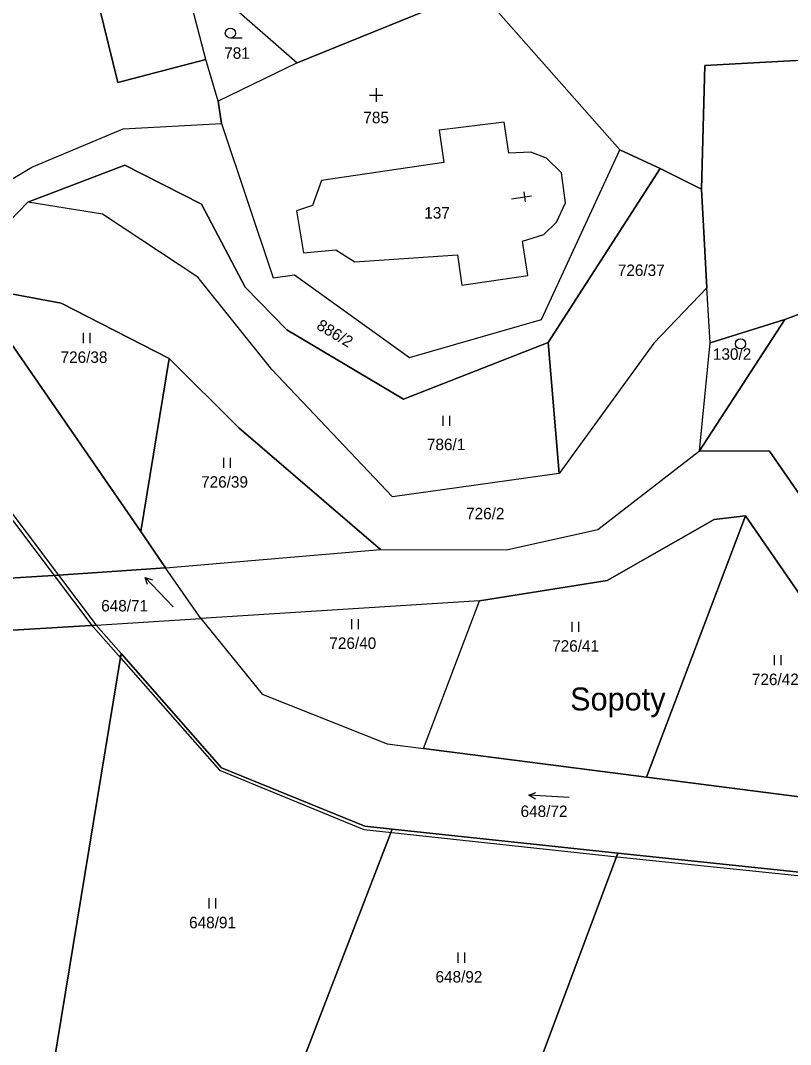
# Model space of a CAD drawing. Extents: x -654083 to -650132, y -1099819 to -1096699.
# Drawn here: x -653142.9 to -653028.7, y -1098349.3 to -1098197.5 of the extents above; entities that cross this region are included whole.
import ezdxf

# ---------------------------------------------------------------- set-up
doc = ezdxf.new("R2010")
doc.units = 0
for name, color, linetype in [('Obvody jako plochy', 7, 'Continuous'), ('Ostatní hranice', 7, 'Continuous'), ('Ostatní mapové značky 1', 7, 'Continuous'), ('Parcelní čísla', 7, 'Continuous'), ('Značky kultur', 7, 'Continuous')]:
    doc.layers.add(name, color=color, linetype=linetype)

msp = doc.modelspace()

# ---------------------------------------------------------------- linework, layer by layer
at = {"layer": 'Obvody jako plochy'}
for points in [[(-653140.06, -1098171.16), (-653142.69, -1098158.75), (-653160.81, -1098164.87), (-653165.45, -1098167.24), (-653166.29, -1098184.39), (-653163.28, -1098198.26), (-653156.38, -1098205.89), (-653150.52, -1098224.84), (-653141.18, -1098219.21), (-653127.65, -1098213.56), (-653113.09, -1098212.74), (-653113.57, -1098209.43), (-653115.41, -1098203.29), (-653128.45, -1098206.67), (-653133.29, -1098186.91), (-653120.36, -1098183.92), (-653123.61, -1098174.68), (-653124.29, -1098173.63), (-653125.55, -1098167.69), (-653129.48, -1098168.54)], [(-653079.59, -1098187.95), (-653094, -1098190.37), (-653107.31, -1098170.36), (-653104.62, -1098168.32), (-653108.47, -1098163.66), (-653111.39, -1098164.65), (-653125.55, -1098167.69), (-653124.29, -1098173.63), (-653123.61, -1098174.68), (-653115.58, -1098183.94), (-653113.62, -1098191.47), (-653118.1, -1098192.78), (-653120.36, -1098183.92), (-653133.29, -1098186.91), (-653128.45, -1098206.67), (-653115.41, -1098203.29), (-653117.7, -1098194.34), (-653112.47, -1098194.44), (-653101.85, -1098203.76), (-653075.01, -1098192.86)], [(-653128.45, -1098206.67), (-653115.41, -1098203.29), (-653117.7, -1098194.34), (-653118.1, -1098192.78), (-653120.36, -1098183.92), (-653133.29, -1098186.91)], [(-653054.02, -1098216.68), (-653075.01, -1098192.86), (-653101.85, -1098203.76), (-653113.57, -1098209.43), (-653113.09, -1098212.74), (-653105.4, -1098235.64), (-653102.24, -1098235.17), (-653085.2, -1098247.42), (-653065.64, -1098241.83)], [(-653101.85, -1098203.76), (-653113.57, -1098209.43), (-653115.41, -1098203.29), (-653117.7, -1098194.34), (-653112.47, -1098194.44)], [(-653009.72, -1098222.06), (-653004.59, -1098221.2), (-653000.75, -1098231.78), (-653018.05, -1098237.54), (-653029.55, -1098241.81), (-653040.62, -1098245.28), (-653041.08, -1098237.12), (-653041.91, -1098222.49), (-653041.39, -1098204.15), (-653027.83, -1098203.43), (-653014.45, -1098203.06), (-653011.55, -1098222.36)], [(-653127.42, -1098218.94), (-653141.81, -1098224.4), (-653151.72, -1098234.65), (-653155.1, -1098229.74), (-653150.52, -1098224.84), (-653141.18, -1098219.21), (-653127.65, -1098213.56), (-653113.09, -1098212.74), (-653105.4, -1098235.64), (-653102.24, -1098235.17), (-653085.2, -1098247.42), (-653065.64, -1098241.83), (-653054.02, -1098216.68), (-653048.02, -1098219.45), (-653064.64, -1098245.21), (-653086.06, -1098253.64), (-653103.37, -1098243.32), (-653109.58, -1098237.03), (-653116.05, -1098224.73)], [(-653063.4, -1098227.37), (-653062.04, -1098224.53), (-653062.64, -1098220.09), (-653064.88, -1098217.9), (-653067.21, -1098216.99), (-653070.45, -1098217.14), (-653071.17, -1098212.57), (-653080.78, -1098213.77), (-653080.08, -1098218.55), (-653098.25, -1098221.22), (-653099.57, -1098224.91), (-653101.96, -1098225.69), (-653100.91, -1098231.95), (-653096.13, -1098231.5), (-653093.28, -1098233.27), (-653078.09, -1098232.25), (-653077.44, -1098236.72), (-653067.67, -1098235.29), (-653068.42, -1098230.21), (-653065.25, -1098229.21)], [(-653078.09, -1098232.25), (-653077.44, -1098236.72), (-653067.67, -1098235.29), (-653068.42, -1098230.21), (-653065.25, -1098229.21), (-653063.4, -1098227.37), (-653062.04, -1098224.53), (-653062.64, -1098220.09), (-653064.88, -1098217.9), (-653067.21, -1098216.99), (-653070.45, -1098217.14), (-653071.17, -1098212.57), (-653080.78, -1098213.77), (-653080.08, -1098218.55), (-653098.25, -1098221.22), (-653099.57, -1098224.91), (-653101.96, -1098225.69), (-653100.91, -1098231.95), (-653096.13, -1098231.5), (-653093.28, -1098233.27)], [(-653068.42, -1098230.21), (-653065.25, -1098229.21), (-653063.4, -1098227.37), (-653062.04, -1098224.53), (-653062.64, -1098220.09), (-653064.88, -1098217.9), (-653067.21, -1098216.99), (-653070.45, -1098217.14), (-653071.17, -1098212.57), (-653080.78, -1098213.77), (-653080.08, -1098218.55), (-653098.25, -1098221.22), (-653099.57, -1098224.91), (-653101.96, -1098225.69), (-653100.91, -1098231.95), (-653096.13, -1098231.5), (-653093.28, -1098233.27), (-653078.09, -1098232.25), (-653077.44, -1098236.72), (-653067.67, -1098235.29)], [(-653064.64, -1098245.21), (-653063.01, -1098264.63), (-653087.72, -1098268.11), (-653105.63, -1098249.24), (-653116.57, -1098235.54), (-653130.71, -1098226.18), (-653141.81, -1098224.4), (-653127.42, -1098218.94), (-653116.05, -1098224.73), (-653109.58, -1098237.03), (-653103.37, -1098243.32), (-653086.06, -1098253.64)], [(-653041.91, -1098222.49), (-653041.08, -1098237.12), (-653048.96, -1098245.31), (-653063.01, -1098264.63), (-653064.64, -1098245.21), (-653048.02, -1098219.45)], [(-653048.96, -1098245.31), (-653063.01, -1098264.63), (-653087.72, -1098268.11), (-653105.63, -1098249.24), (-653116.57, -1098235.54), (-653130.71, -1098226.18), (-653141.81, -1098224.4), (-653151.72, -1098234.65), (-653150.15, -1098236.92), (-653136.87, -1098239.39), (-653120.82, -1098247.61), (-653110.51, -1098257.89), (-653089.48, -1098275.9), (-653070.83, -1098275.94), (-653057.26, -1098272.93), (-653042.19, -1098261.25), (-653040.62, -1098245.28), (-653041.08, -1098237.12)], [(-653120.82, -1098247.61), (-653136.87, -1098239.39), (-653150.15, -1098236.92), (-653125.05, -1098273.25)], [(-653018.05, -1098237.54), (-652987.91, -1098261.96), (-653004.68, -1098300.48), (-653031.8, -1098261.34), (-653042.19, -1098261.25), (-653029.55, -1098241.81)], [(-653040.62, -1098245.28), (-653029.55, -1098241.81), (-653042.19, -1098261.25)], [(-653168.56, -1098281.61), (-653189.13, -1098265.9), (-653162.58, -1098246.05), (-653137.26, -1098279.68)], [(-653089.48, -1098275.9), (-653110.51, -1098257.89), (-653120.82, -1098247.61), (-653125.05, -1098273.25), (-653121.36, -1098278.59)], [(-652999.64, -1098308.34), (-652994.97, -1098318.86), (-653005.77, -1098316.31), (-653008.41, -1098309.88), (-653035.35, -1098270.9), (-653039.99, -1098271.44), (-653055.86, -1098280.51), (-653074.8, -1098283.51), (-653116.16, -1098286.11), (-653121.36, -1098278.59), (-653089.48, -1098275.9), (-653070.83, -1098275.94), (-653057.26, -1098272.93), (-653042.19, -1098261.25), (-653031.8, -1098261.34), (-653004.68, -1098300.48)], [(-653137.26, -1098279.68), (-653131.67, -1098287.09), (-653177, -1098289.83), (-653195.41, -1098271.81), (-653196.78, -1098270.13), (-653190.76, -1098264.59), (-653189.13, -1098265.9), (-653168.56, -1098281.61)], [(-653035.35, -1098270.9), (-653050.07, -1098309.63), (-653083.12, -1098305.39), (-653074.8, -1098283.51), (-653055.86, -1098280.51), (-653039.99, -1098271.44)], [(-653008.41, -1098309.88), (-653010.75, -1098315.14), (-653015.05, -1098314.13), (-653050.07, -1098309.63), (-653035.35, -1098270.9)], [(-653127.95, -1098291.32), (-653142.71, -1098381.19), (-653171.11, -1098374.64), (-653176.09, -1098376.64), (-653195.41, -1098271.81), (-653177, -1098289.83), (-653131.67, -1098287.09)], [(-653131.67, -1098287.09), (-653116.16, -1098286.11), (-653121.36, -1098278.59), (-653137.26, -1098279.68)], [(-653107.03, -1098297.32), (-653088.53, -1098304.7), (-653083.12, -1098305.39), (-653074.8, -1098283.51), (-653116.16, -1098286.11)], [(-653005.77, -1098316.31), (-653000.43, -1098329.34), (-653015.1, -1098325.02), (-653054.32, -1098320.92), (-653087.77, -1098317.34), (-653091.81, -1098316.91), (-653113.07, -1098308.24), (-653127.95, -1098291.32), (-653131.67, -1098287.09), (-653116.16, -1098286.11), (-653107.03, -1098297.32), (-653088.53, -1098304.7), (-653083.12, -1098305.39), (-653050.07, -1098309.63), (-653015.05, -1098314.13), (-653010.75, -1098315.14)], [(-653091.81, -1098316.91), (-653087.77, -1098317.34), (-653114.87, -1098387.6), (-653142.71, -1098381.19), (-653127.95, -1098291.32), (-653113.07, -1098308.24)], [(-653054.32, -1098320.92), (-653084.9, -1098402.68), (-653099.09, -1098391.24), (-653114.87, -1098387.6), (-653087.77, -1098317.34)], [(-653015.1, -1098325.02), (-653060.71, -1098431.71), (-653075.36, -1098410.36), (-653084.9, -1098402.68), (-653054.32, -1098320.92)]]:
    msp.add_lwpolyline(points, close=True, dxfattribs=at)
for points in [[(-653027.83, -1098203.43), (-653041.39, -1098204.15), (-653041.91, -1098222.49), (-653048.02, -1098219.45), (-653054.02, -1098216.68), (-653075.01, -1098192.86)], [(-653162.58, -1098246.05), (-653137.26, -1098279.68), (-653121.36, -1098278.59), (-653125.05, -1098273.25), (-653150.15, -1098236.92)]]:
    msp.add_lwpolyline(points, dxfattribs=at)
for radius in [0.75, 0.001]:
    msp.add_circle((-653036.1, -1098245.41), radius, dxfattribs=at)
at = {"layer": 'Ostatní hranice'}
for p, q in [((-653132.1, -1098287.35), (-653164.48, -1098244.54)), ((-653132.1, -1098287.35), (-653128.34, -1098291.63)), ((-653128.34, -1098291.63), (-653113.39, -1098308.62)), ((-653113.39, -1098308.62), (-653091.99, -1098317.38)), ((-653091.99, -1098317.38), (-653087.83, -1098317.84)), ((-653087.83, -1098317.84), (-653054.39, -1098321.42)), ((-653054.39, -1098321.42), (-653015.28, -1098325.49))]:
    msp.add_line(p, q, dxfattribs=at)
at = {"layer": 'Ostatní mapové značky 1'}
for p, q in [((-653067.98, -1098224.38), (-653068.2, -1098222.9)), ((-653070.07, -1098223.93), (-653067.1, -1098223.5))]:
    msp.add_line(p, q, dxfattribs=at)
at = {"layer": 'Značky kultur'}
for p, q in [((-653110.01, -1098200.11), (-653111.76, -1098200.11)), ((-653090.13, -1098207.54), (-653090.13, -1098209.54)), ((-653091.13, -1098208.54), (-653089.13, -1098208.54)), ((-653133.59, -1098243.8), (-653133.59, -1098245.3)), ((-653132.57, -1098245.3), (-653132.57, -1098243.8)), ((-653080.25, -1098256.07), (-653080.25, -1098257.57)), ((-653079.22, -1098257.57), (-653079.22, -1098256.07)), ((-653112.78, -1098262.29), (-653112.78, -1098263.79)), ((-653111.76, -1098263.79), (-653111.76, -1098262.29)), ((-653120.23, -1098284.37), (-653124.37, -1098280.03)), ((-653093.8, -1098286.2), (-653093.8, -1098287.7)), ((-653092.78, -1098287.7), (-653092.78, -1098286.2)), ((-653061.1, -1098286.6), (-653061.1, -1098288.1)), ((-653060.08, -1098288.1), (-653060.08, -1098286.6)), ((-653031.11, -1098291.55), (-653031.11, -1098293.05)), ((-653030.08, -1098293.05), (-653030.08, -1098291.55)), ((-653061.51, -1098312.67), (-653067.51, -1098312.33)), ((-653114.94, -1098327.59), (-653114.94, -1098329.09)), ((-653113.92, -1098329.09), (-653113.92, -1098327.59)), ((-653078.03, -1098335.64), (-653078.03, -1098337.14)), ((-653077.01, -1098337.14), (-653077.01, -1098335.64))]:
    msp.add_line(p, q, dxfattribs=at)
for points in [[(-653124.04, -1098281.1), (-653124.37, -1098280.03), (-653123.32, -1098280.41)], [(-653066.53, -1098312.89), (-653067.51, -1098312.33), (-653066.48, -1098311.89)]]:
    msp.add_lwpolyline(points, dxfattribs=at)
msp.add_circle((-653111.76, -1098199.36), 0.75, dxfattribs=at)

# ---------------------------------------------------------------- texts
at = {"layer": 'Obvody jako plochy'}
msp.add_text('Sopoty', height=3.4, dxfattribs=at).set_placement((-653061.38, -1098299.75))
at = {"layer": 'Parcelní čísla'}
for s, p in [('781', (-653112.67, -1098203.17)), ('785', (-653092.04, -1098212.72)), ('137', (-653083, -1098226.85)), ('726/37', (-653054.3, -1098235.36)), ('726/38', (-653136.94, -1098248.24)), ('130/2', (-653040.2, -1098247.78)), ('786/1', (-653082.61, -1098261.17)), ('726/39', (-653116.1, -1098266.73)), ('726/2', (-653076.8, -1098271.42)), ('648/71', (-653130.91, -1098285.08)), ('726/40', (-653097.08, -1098290.63)), ('726/41', (-653064.04, -1098291.04)), ('726/42', (-653034.42, -1098295.99)), ('648/72', (-653068.72, -1098315.54)), ('648/91', (-653117.88, -1098332.03)), ('648/92', (-653081.34, -1098340.07))]:
    msp.add_text(s, height=1.7, dxfattribs=at).set_placement(p)
msp.add_text('886/2', height=1.7, rotation=329.22, dxfattribs=at).set_placement((-653099.12, -1098243.13))

doc.saveas('drawing.dxf')
